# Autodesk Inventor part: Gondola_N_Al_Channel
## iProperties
Shininess: 64.0
Length Units: 11272
Angle Units: 11279
Time Units: 11290
Mass Units: 11286
Length Display Precision: 3
Angle Display Precision: 2
Compacted: True
Part Number: Gondola_N_Al_Channel
Document SubType Name: Modeling
Created: 2004-12
Designer: John Blackburn
Material: Aluminum-6061
Description: AL. Assoc. 8" 6061-T6 Channel
Manufacturer: Standard
Standards Organization: Custom
Density: 0.0
Volumn: 0.0
Area: 0.0
PropertySet Name: Model Information
Control State: 0
Master: False
Checked Out: False
Author: John Blackburn
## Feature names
1. Extrusion1
2. Hole1
3. Hole2
4. Hole3
5. Hole4
6. Hole5
7. Hole6
8. Hole7
